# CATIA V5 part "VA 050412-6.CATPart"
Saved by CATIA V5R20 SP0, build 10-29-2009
Part number: VA 050412-6
Revision: ANY
Definition: UNKNOWN
Nomenclature: VA 050412-6
Source: Unknown
Bounding box of the stored display mesh (mm): x -1.85 to 1.85, y 0 to 1.25, z -1.85 to 1.85
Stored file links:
  C:\Users\Utente\Desktop\IO LAVORO\3D X SITO CF\CUMSA\3D files VA\VA 050412\VA 050412-6.CATPart
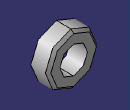
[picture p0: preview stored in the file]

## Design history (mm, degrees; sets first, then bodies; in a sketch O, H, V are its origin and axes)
Body1 "Revolución1" (main body)
  Solid1: solid without history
